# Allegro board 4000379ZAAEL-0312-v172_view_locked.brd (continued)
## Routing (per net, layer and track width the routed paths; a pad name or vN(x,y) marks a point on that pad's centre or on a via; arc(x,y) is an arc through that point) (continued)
MDIDP2: length 28
  TOP w0.091: v3(134.49,109.98) 134.64,110.13 134.64,111.03 134.55,111.12 133.93,111.12 D73.1 133.99,111.57 134.36,111.57 134.45,111.66 134.45,113.2 133.99,113.66 T2.11
  BOTTOM w0.091: U66.65 120.2,96 121.67,97.47 122.83,97.47 134.61,109.26 134.61,109.86 v3(134.49,109.98)
MDIO: length 122.9
  TOP w0.102: E1U1.29 71.32,94.69 70.36,93.73 68.33,93.73 67.94,93.34 67.25,93.34 v1(67.06,93.54)
  TOP w0.127: v1(109.6,68.14) 109.86,68.14 110.87,67.12 110.87,61.02 110.11,60.26 110.11,59.87 SR608.2 ; v1(93.6,73.53) 93.34,73.53 90.04,70.23 v1(90.04,68.71) ; SR57.2 SR70.2 108.14,77.28 108.15,77.26 SC266.1 R234.2 110.16,77.26 v1(110.43,77.53)
  L3 w0.127: v1(109.6,68.14) 109.6,68.33 109.35,68.58 90.17,68.58 v1(90.04,68.71) 89.79,68.45 70.93,68.45 67.56,71.82 67.56,79.76 64.96,82.36 64.96,92.84 65.47,93.34 66.87,93.34 v1(67.06,93.54) ; v1(93.6,73.53) 93.6,73.72 97.66,77.79 110.24,77.79 110.43,77.6 v1(110.43,77.53)
  BOTTOM w0.127: U66.134 115.95,84.53 114.16,82.74 114.16,80.69 111.19,77.72 110.62,77.72 v1(110.43,77.53)
MDIO_0: length 9.8
  TOP w0.102: U1.W6 108.22,52.18 v1(108.15,52.18)
  TOP w0.127: SR608.1 109.73,58.36 108.78,57.4 v1(108.71,57.4)
  L3 w0.127: v1(108.15,52.18) 108.14,52.18 107.84,51.88 107.19,51.88 106.93,52.13 106.93,53.34 107.16,53.57 107.44,53.57 107.75,53.87 107.75,54.91 107.98,55.14 107.98,56.67 v1(108.71,57.4)
MPD: length 9.6
  TOP w0.254: U602.9 v4(54.87,32.45) ; U601.16 58.82,37.26 v4(58.44,37.26)
  BOTTOM w0.254: v4(58.44,37.26) 58.44,37.35 arc(57.9,37.71) 57.26,37.84 56.79,37.84 arc(56.35,37.75) 55.98,37.5 55.6,37.12 arc(55.06,36.31) 54.87,35.35 v4(54.87,32.45)
MSCL0_MSCK: length 5.7
  BOTTOM w0.127: SR603.2 SR611.2 SC502.1 112.8,82.11 112.8,82.82 113.62,83.65 114.07,83.65 114.95,84.53 U66.138
MSCL1_MOSI: length 7.7
  BOTTOM w0.127: SR612.2 SR604.2 ; SR612.2 SC501.1 110.46,82.63 112.23,82.63 113.56,83.97 113.94,83.97 114.45,84.47 U66.140 ; SR612.2 108.97,82.11
MSDA0_MISO: length 10.1
  BOTTOM w0.127: U66.142 113.95,84.42 113.81,84.29 113.43,84.29 112.1,82.95 110.26,82.95 109.86,82.55 107.52,82.55 SC500.1 SR613.2 SR605.2
MSDA1_MCSN: length 12.3
  BOTTOM w0.127: SR606.2 SC499.1 SR614.2 104.68,82.57 107.15,82.57 107.38,82.8 109.73,82.8 110.13,83.21 111.89,83.21 U66.144
OPT_RX_LOS: length 77
  TOP w0.102: U601.31 61.56,32.61 61.65,32.52 61.65,30.72 R605.2 61.42,29.83 v1(61.43,29.82) ; R233.2 98.95,57.21 100.2,57.21 100.9,56.52 102.04,56.52 102.62,55.93 102.62,55.19 U1.AG20
  TOP w0.127: v1(90.36,60.2) 90.36,60.71 92.14,62.48 96.46,62.48 97.66,61.28 97.66,58.24 97.92,57.99 R233.2
  L3 w0.127: v1(61.43,29.82) 60.58,30.67 60.58,32.26 62.23,33.91 62.23,52.26 66.93,56.96 81.03,56.96 84.26,60.2 v1(90.36,60.2)
OPT_TX_SD: length 93.4
  TOP w0.102: U601.23 58.29,33.99 57.34,33.04 v1(57.34,32.26) ; U1.AE12 106.07,54.74 106.4,55.07 106.4,55.3 106.28,55.41 106.28,55.74 107.44,56.9 107.44,57.79 107.82,58.17 108.32,58.17 R277.2
  TOP w0.127: v1(79.95,60.77) 80.58,60.77 87.38,67.56 105.22,67.56 108.46,64.33 108.46,60.71 109.22,59.94 109.22,58.86 108.98,58.63 R277.2
  L3 w0.127: v1(57.34,32.26) 57.34,32.55 59.12,34.33 59.12,37.68 58.8,38 58.8,53.33 64.86,59.39 78.57,59.39 v1(79.95,60.77)
OPT_TXFAULT: length 83.7
  TOP w0.102: R232.2 107.19,57.99 107.19,56.96 106.08,55.85 106.08,55.19 U1.AG12
  TOP w0.127: U601.9 61.96,37.51 62.17,37.72 64.39,37.72 v1(64.45,37.66) 64.52,37.72 64.72,37.72 R606.2 ; v1(82.87,56.96) 82.87,57.02 82.74,57.15 82.74,57.72 81.03,59.44 81.03,60.83 87.5,67.31 103.38,67.31 107.25,63.44 107.25,60.26 107.38,60.13 107.38,58.8 107.55,58.63 R232.2
  L3 w0.127: v1(82.87,56.96) 82.87,56.95 82.87,56.77 81.79,55.69 68.39,55.69 64.01,51.31 64.01,38.1 v1(64.45,37.66)
P4_LED2: length 4.3
  TOP w0.127: v1(109.66,89.98) 108.63,89.98 SC268.2
  BOTTOM w0.127: U66.20 112.08,90.36 111.7,89.98 111.19,89.98 TP12.1 110.55,90.42 110.11,89.98 v1(109.66,89.98)
PON_RX_SLEEP: length 78.6
  TOP w0.102: R258.2 102.36,57.47 103.49,56.34 103.49,55.18 U1.AG18
  TOP w0.127: U601.27 59.96,32.27 v4(59.88,32.19) ; R258.2 102.09,57.99 101.85,58.23 101.85,61.4 99.25,64.01 89.85,64.01 88.2,62.36 v1(88.2,61.66)
  L3 w0.127: v1(88.2,61.66) 81.47,61.66 78.95,59.14 64.99,59.14 59.05,53.21 59.05,38.16 59.37,37.85 59.37,32.7 v4(59.88,32.19)
  BOTTOM w0.127: v4(59.88,32.19) 59.84,32.23 C602.1
PON_TX_DIS: length 69.6
  TOP w0.102: R231.2 99.65,57.47 100.27,57.47 101.03,56.71 102.17,56.71 102.83,56.05 102.83,55.43 102.94,55.31 102.94,55.06 102.62,54.74 U1.AE20
  TOP w0.127: R604.2 65.05,38.24 R613.1 v1(62.93,38.24) 62.18,38.24 61.56,37.62 U601.10 ; v1(89.79,59.37) 89.79,60.55 91.97,62.74 97.35,62.74 98.68,61.4 98.68,58.24 98.93,57.99 R231.2
  L3 w0.127: v1(62.93,38.24) 63.12,38.43 63.12,51.78 67.66,56.32 81.22,56.32 84.26,59.37 v1(89.79,59.37)
PSE_54V0_P1+: length 242.2
  TOP w0.254: v4(31.72,136.75) 31.88,136.91 31.88,137.29 31.97,137.38 U909.28
  TOP w0.635: C252.1 94.61,129.12 T17.45 ; T17.33 106.83,130.91 v2(106.81,130.94)
  TOP w0.762: T1.21 73.91,130.3 73.41,130.81 C244.1 73.79,131.91 74.55,132.67 v2(74.55,136.14) v2(74.55,138.3) ; C252.1 94.11,132.8 93.34,133.56 v2(93.34,135.64) v2(93.34,138.68) ; v2(106.81,130.94) C257.1 ; D814.1 50.24,144.32 C8577.1 v2(52.51,144.32) ; v2(58.1,138.75) 58.55,138.3 58.55,131.13 v2(58.04,130.62) 58.1,130.56 58.1,128.65 57.1,127.65 C8574.1 55.64,127.65 D809.1 51.18,123.2 v2(51.18,123.19) 51.18,118.52 R496.1 51.21,115.61 R1014.1 ; C248.1 v2(125.09,130.94) T2.21
  BOTTOM w0.762: v2(106.81,130.94) 105.28,129.41 D121.2 D102.1 ; v2(106.81,130.94) 105.66,132.08 59.5,132.08 v2(58.04,130.62) 57.17,130.62 56.64,131.15 C8575.1 55.47,131.15 54,129.67 D811.1 ; v2(106.81,130.94) 107.7,131.83 124.21,131.83 v2(125.09,130.94) 123.52,130.94 D117.2 D84.1 ; 53.71,141.73 D813.1 56.52,138.93 C8576.1 56.53,138.75 v2(58.1,138.75) 58.74,138.75 61.34,136.14 v2(74.55,136.14) 92.84,136.14 v2(93.34,135.64) ; 53.71,141.73 D820.C 49.74,142.22 48.26,143.7 33.46,143.7 32.32,142.56 32.32,139 31.78,138.46 31.78,137.62 C8573.1 31.8,137.48 31.75,137.43 31.75,136.78 v4(31.72,136.75) ; 53.71,141.73 52.51,142.93 v2(52.51,144.32) ; v2(93.34,138.68) 95.2,140.54 D125.2 D106.1 ; v2(74.55,138.3) 75.11,138.3 D113.2 D80.1 ; v2(51.18,123.19) 51.18,125.13 50.1,126.21 D812.C
PSE_54V0_P1-: length 56.2
  TOP w0.635: C258.1 90.55,131.03 91.53,130.05 T17.48
  TOP w0.762: C258.1 90.49,131.97 89.65,131.97 88.9,132.72 v2(88.9,135.13) v2(88.9,137.16)
  BOTTOM w0.762: v2(88.9,135.13) 60.64,135.13 58.4,137.37 C8576.2 54.03,137.37 D813.2 53.84,137.54 F3.2 ; v2(88.9,137.16) 88.9,139.9 D108.1 D126.2
PSE_54V0_P2-: length 36.3
  TOP w0.762: T1.24 C245.1 69.47,131.91 68.71,132.67 v2(68.71,137.16) ; v2(55.94,140.78) 53.7,143.02 51.62,143.02 C8577.2
  BOTTOM w0.762: D82.1 D114.2 68.71,140.03 v2(68.71,137.16) 61.98,137.16 59.05,140.08 56.64,140.08 v2(55.94,140.78)
PSE_54V0_P3-: length 85.2
  TOP w0.762: v2(121.79,138.05) v2(121.79,133.1) 121.79,132.67 120.9,131.78 C249.1 120.52,130.81 121.28,130.05 121.28,129.02 ; v2(57.34,131.83) 56.52,131 56.52,130.3
  TOP w1.016: C8574.2 56.52,130.3
  BOTTOM w0.762: v2(121.79,138.05) 121.79,139.39 D118.2 D86.1 ; v2(121.79,133.1) 58.61,133.1 v2(57.34,131.83)
PSE_54V0_P4-: length 69.9
  TOP w0.635: C253.1 103.77,132.68 T17.36
  TOP w0.762: v2(102.74,138.94) v2(102.74,134.11) 102.74,133.56 103.5,132.8 C253.1
  BOTTOM w0.762: v2(102.74,138.94) 102.74,139.01 D122.2 D104.1 ; F2.1 53.52,133.99 D811.2 53.86,133.72 55.07,132.51 C8575.2 57.99,134.11 v2(102.74,134.11)
PSE_SCL: length 16
  TOP w0.127: U909.3 33.27,133.54 33.53,133.79 33.53,134.37 32.96,134.94 28.96,134.94 26.67,132.65 25.15,132.65 24.32,133.48 24.32,135.19 24.27,135.24 R352.1 U22.6
PSE_SDA: length 17.4
  TOP w0.127: U22.7 R353.1 24.69,135.24 24.6,135.15 24.6,133.58 25.27,132.91 26.54,132.91 28.83,135.19 33.08,135.19 33.78,134.49 33.78,133.68 33.92,133.54 ; 33.92,133.54 34.44,133.54 34.57,133.41 U909.5 ; 33.92,133.54 U909.4
PTP_SYNC: length 8.9
  BOTTOM w0.127: SR390.1 112.78,78.11 115.59,80.92 115.59,83.21 116.95,84.56 U66.130
PWR_0V9_PLL5: length 6.2
  TOP w0.254: 106.1,52.68 U1.AA12 ; 106.1,52.68 106.09,52.69 U1.AA14 ; 106.1,52.68 v1(106.48,53.06)
  BOTTOM w0.254: v1(106.48,53.06) 106.67,53.26 C188.1
  BOTTOM w0.305: FB7.2 106.05,57.06 106.6,56.51 C181.1 106.67,55.62 C194.1 C188.1
PWR_1V8_XFI0: length 3.5
  TOP w0.254: v1(104,53.96) 104.46,53.5 U1.AC16
  BOTTOM w0.305: v1(104,53.96) 104.4,54.36 C180.2 104.4,54.93 104.76,55.29 C235.1 104.76,55.91 FB10.2
PWR_1V8_XFI1: length 7.1
  TOP w0.254: U1.AA8 v1(107.33,52.31)
  BOTTOM w0.203: v1(107.33,52.31) 107.68,52.65 109.57,52.65 C187.2
  BOTTOM w0.305: FB6.2 112.74,52.78 C236.1 109.97,52.78 C187.2
PWR_1V8_XFI2: length 8.9
  TOP w0.254: U1.U8 107.72,51.05 107.42,50.75 v1(107.37,50.75)
  BOTTOM w0.127: 112.73,52.01 C239.1
  BOTTOM w0.203: C193.2 110.71,51.55 110.52,51.36 108.69,51.36 108.38,51.05 107.76,51.05 107.45,50.75 v1(107.37,50.75)
  BOTTOM w0.305: C193.2 110.95,51.63 111.32,52.01 114.39,52.01 114.73,52.35 FB5.2
PWR_DG: length 4.6
  TOP w0.254: v1(100.81,49.94) 100.81,49.85 U1.P25
  BOTTOM w0.203: R66.2 97.31,49.01 R28.2 98.76,49.53 100.08,49.53 100.48,49.94 v1(100.81,49.94)
RESET#: length 14.6
  TOP w0.127: SR143.2 117.78,80.01 116.13,81.66 116.13,84.07 116.48,84.43 SC168.1 116.68,84.43 SR128.1 116.68,86.18 v1(116.61,86.25)
  BOTTOM w0.203: U66.131 116.7,86.16 v1(116.61,86.25)
RESET_BUTTON_N: length 183.5
  TOP w0.102: U1.T3 109.7,50.5 110.16,50.5 110.26,50.6 111.91,50.6 112,50.69 116.55,50.69 118.31,52.45 123.83,52.45
  TOP w0.127: R810.1 50.1,159.26 50.09,159.25 C810.1 C981.2 R809.1 50.09,153.62 63.37,140.34 v1(63.37,95.5) ; v1(121.16,67.06) 121.16,58.23 124.4,54.99 124.4,53.02 123.83,52.45
  L3 w0.127: v1(121.16,67.06) 121.13,67.08 69.57,67.08 65.6,71.06 65.6,79.25 63.37,81.47 v1(63.37,95.5)
RESET_PHY_N: length 109.2
  TOP w0.102: E1R22.1 67.56,94.23 v1(67.22,94.58)
  TOP w0.127: v1(109.57,61.18) 109.03,61.72 109.03,65.6 107.44,67.18 v1(107.44,67.75) ; U1.AB27 99.3,52.92 98.84,52.92 98.6,52.68 98.1,52.68 96.8,53.98 95.2,53.98 92.63,56.54 92.63,61.14 v1(92.84,61.34)
  L3 w0.127: v1(107.44,67.75) 107.28,67.59 70.33,67.59 66.48,71.44 66.48,79.63 64.14,81.98 64.14,93.92 65.02,94.81 66.99,94.81 v1(67.22,94.58) ; v1(92.84,61.34) 93.28,61.79 108.97,61.79 v1(109.57,61.18)
RESET_RTL8261BE_N: length 14.3
  TOP w0.102: E1U1.28 71.34,95.09 71.18,94.93 69.9,94.93 ; 69.58,94.74 68.01,94.74 67.12,95.63 67.12,100.46 67.88,101.22 68.64,101.22 ; 68.64,101.22 E1R3.2 ; 68.64,101.22 EC340.2
  TOP w0.127: E1R22.2 E1R20.1 69.9,94.93
RESET_SUICIDE: length 4
  TOP w0.102: U1.AH6 108.55,55.59 108.55,56.29 109.97,57.71 v1(110.4,57.71)
  BOTTOM w0.127: R963.1 110.74,58.04 v1(110.4,57.71)
RESETB: length 7
  TOP w0.127: SR143.1 126.06,80.01 SR90.2 SR88.2 128.31,80.06 SD2.A 129.2,80.77 SC254.1 130.24,80.76 U108.RST
RSET0: length 2.4
  TOP w0.203: E1R5.2 80.57,100.99 80.57,99.34 80.31,99.09 E1U1.68
RSSI: length 3.8
  BOTTOM w0.381: R660.1 56.29,25.5 56.86,24.93 56.86,23.84 56.47,23.46 R655.2 56.02,23.29 Q603.3
RSSI_IN: length 9.6
  TOP w0.229: C603.1 58.89,31.94 59.49,32.54 arc(59.54,32.61) 59.56,32.7 U601.26
  TOP w0.508: v4(57.15,30.8) 58.05,30.8 58.83,31.58 C603.1
  BOTTOM w0.508: R660.2 57.61,26.12 57.61,27.62 56.83,28.41 56.83,30.48 v4(57.15,30.8)
RSV_TEST0: length 1.8
  TOP w0.305: SR536.1 124.14,92.33 v1(123.92,92.55)
  BOTTOM w0.203: U66.80 123.46,92.86 123.77,92.55 v1(123.92,92.55)
RXIN1_N: length 5.9
  TOP w0.107: U602.4 55.31,28.89 55.63,29.21 58.69,29.21 59.88,30.4 C600.2
RXIN1_P: length 5.6
  TOP w0.107: C601.2 59.64,30.56 58.57,29.49 55.6,29.49 55.4,29.69 U602.5
RXIN_N: length 2.2
  TOP w0.107: U601.28 60.36,32.86 60.43,32.79 60.43,31.36 60.29,31.23 C601.1
RXIN_P: length 2.4
  TOP w0.107: C600.1 60.5,31.03 60.71,31.24 60.71,32.77 60.76,32.82 U601.29
RXOUT+: length 1.9
  TOP w0.107: C610.2 64.06,34.33 62.7,34.33 62.64,34.39 U601.3
RXOUT-: length 1.9
  TOP w0.107: C609.2 64.08,34.05 62.75,34.05 62.69,33.99 U601.2
RXOUTN: length 73.6
  TOP w0.107: C609.1 64.96,34.06 66.44,34.06 v1(66.67,33.83) ; v1(87.25,57.34) 87.06,57.53 87.06,62.36 89.6,64.9 101.41,64.9 103.25,63.06 103.25,60.39 104.01,59.63 104.01,56.95 104.24,56.72 104.24,55.67 arc(104.23,55.58) 104.19,55.5 arc(104.19,55.49) 104.19,55.49 arc(104.16,55.45) 104.13,55.41 arc(104.12,55.39) 104.1,55.37 104.1,55.37 arc(104.05,55.3) 104.04,55.22 104.04,54.88 U1.AF17
  L3 w0.099: v1(66.67,33.83) 66.89,34.05 67.96,34.05 68.96,35.05 68.96,50.48 71.14,52.66 82.95,52.66 87.06,56.77 87.06,57.15 v1(87.25,57.34)
RXOUTP: length 73.5
  TOP w0.107: v1(66.67,34.57) 66.44,34.34 64.96,34.34 C610.1 ; v1(86.55,57.34) 86.78,57.57 86.78,62.47 89.48,65.18 101.53,65.18 103.53,63.17 103.53,60.5 104.29,59.74 104.29,57.06 104.52,56.83 104.52,55.67 arc(104.5,55.51) 104.43,55.36 arc(104.39,55.29) 104.35,55.23 U1.AG16
  L3 w0.099: v1(86.55,57.34) 86.76,57.13 86.76,56.89 82.82,52.96 71.01,52.96 68.66,50.61 68.66,35.18 67.83,34.35 66.9,34.35 v1(66.67,34.57)
S0RXN: length 7.9
  BOTTOM w0.091: U66.122 118.95,84.76 119.04,84.67 119.04,84.14 118.65,83.74 118.65,83.36 117.73,82.44 117.73,79.68 117.73,77.9 SR259.1
S0RXP: length 8.6
  BOTTOM w0.091: U66.123 118.7,84.28 118.3,83.88 118.3,83.5 117.38,82.59 117.38,79.68 117.39,77.87 SR260.1
S0TXN: length 8.7
  BOTTOM w0.091: U66.119 119.7,83.78 119.34,83.42 119.34,83.04 119.01,82.71 119.01,80.12 119.79,79.35 119.79,77.87 SC85.1
S0TXP: length 8
  BOTTOM w0.091: U66.120 119.38,84.69 119.38,83.95 119,83.57 119,83.19 118.67,82.85 118.67,79.98 119.44,79.2 119.44,77.9 SC84.1
SCL_M: length 2.7
  BOTTOM w0.127: U604.6 47.39,25.46 R630.1 47.86,25.49 48.23,25.49 R639.1
SDA_M: length 2.6
  BOTTOM w0.127: U604.5 47.57,26.11 R629.1 47.87,25.92 48.27,25.92 R633.1
SEL_XTAL: length 3.1
  TOP w0.254: v1(121.16,86.79) 121.11,86.84 121.04,86.84 120.83,87.06 SR73.2 120.51,86.27 SR72.1
  BOTTOM w0.203: v1(121.16,86.79) 121.2,86.83 121.48,86.83 121.76,87.11 U66.103
SPF_CS#: length 27.9
  BOTTOM w0.089: 111.85,87.46 112,87.61 U66.9
  BOTTOM w0.127: 111.85,87.46 111.13,86.74 109.98,86.74 109.6,86.36 105.38,86.36 103.82,87.92 103.82,95.76 102.3,97.28 97.79,97.28 97.54,97.03 TP24.1 97.54,95.47 97.56,95.44 ; 97.56,95.44 SC256.1 ; 97.56,95.44 SR142.2
SPF_SCK: length 8
  BOTTOM w0.127: SR140.2 SC250.1 106.72,84.29 107.04,83.97 108.61,83.97 TP21.1 109.41,85.03 110.36,85.98 111.63,85.98 112.02,86.36 U66.4
SPF_SI: length 7.6
  BOTTOM w0.127: SR141.2 SC252.1 106.7,85.68 106.87,85.85 108.33,85.85 TP22.1 109.54,85.53 110.24,86.23 111.44,86.23 112.07,86.86 U66.6
SPF_SO: length 21.6
  BOTTOM w0.127: SR139.2 SC251.1 102.04,96.77 TP23.1 103.57,95.25 103.57,87.77 105.23,86.11 109.73,86.11 110.11,86.49 111.25,86.49 112.13,87.36 U66.8
SPI1_CS#: length 3.8
  BOTTOM w0.127: 97.52,92.65 98.43,92.65 98.89,93.11 U7.1 ; 97.52,92.65 SR80.2 ; 97.52,92.65 97.52,93.6 SR142.1
SPI1_HOLD#: length 2.6
  BOTTOM w0.508: SR81.2 SC523.1 100.16,85.64 U7.7
SPI1_SCK: length 5.2
  BOTTOM w0.127: U7.6 101.43,85.73 102.66,84.5 SR82.2 104.91,84.5 SR140.1
SPI1_SI: length 3.3
  BOTTOM w0.127: U7.5 102.7,86.21 103.49,85.42 SR85.2 103.96,85.41 SR141.1
SPI1_SO: length 6.1
  BOTTOM w0.127: SR98.2 97.54,91.65 98.89,91.65 100.16,92.92 U7.2 100.16,95.42 100.15,95.43 SR139.1
SPI1_WP#: length 8.2
  BOTTOM w0.127: SR87.1 SR84.2 100.33,90.68 101.73,92.07 101.73,93.54 101.43,93.83 U7.3
SWITCH_INT_N: length 58
  TOP w0.127: v4(109.35,73.09) 109.35,72.33 108.33,71.31 108.33,66.67 109.28,65.72 109.28,62.17 109.54,61.91 v1(109.54,61.85) ; v1(92.2,61.59) 92.32,61.48 92.32,56.4 95.06,53.66 96.71,53.66 97.97,52.4 98.78,52.4 U1.AA28
  L3 w0.127: v1(92.2,61.59) 92.65,62.04 109.41,62.04 109.54,61.91 v1(109.54,61.85)
  BOTTOM w0.127: U66.132 116.45,84.44 115.34,83.33 115.34,81.05 112.2,77.91 112.2,75.95 v4(109.35,73.09)
SWITCH_RESET_N: length 62.3
  TOP w0.102: 96.84,52.07 97.54,52.07 97.74,51.87 98.68,51.87 99.35,52.54 U1.AA26
  TOP w0.127: 96.84,52.07 96.22,52.07 92.01,56.27 92.01,60.83 v1(91.79,61.06) ; SR63.2 115.82,85.37 SR128.2 115.82,85.37 115.82,80.47 v1(115.09,79.73) ; v1(110.64,73.25) 108.58,71.2 108.58,66.8 109.54,65.85 109.54,62.67 v1(110.17,62.04)
  L3 w0.127: v1(110.17,62.04) 109.92,62.29 92.14,62.29 91.63,61.79 91.63,61.21 v1(91.79,61.06)
  BOTTOM w0.127: v1(115.09,79.73) 113.28,77.93 113.28,75.9 v1(110.64,73.25)
TX_BURST: length 79.8
  TOP w0.102: U1.AF13 105.75,54.87 105.75,55.29 105.88,55.42 105.88,55.97 106.93,57.02 106.93,58.37 R621.1
  TOP w0.127: R699.2 65.1,39.61 64.83,39.88 v1(64.71,39.88) 62.44,39.88 R623.1 ; R621.1 106.95,58.63 107.12,58.8 107.12,60.01 107,60.13 107,63.25 103.19,67.06 87.63,67.06 81.28,60.71 81.28,59.56 v1(83.38,57.47)
  L3 w0.127: v1(83.38,57.47) 83.38,56.83 81.98,55.44 69.53,55.44 64.9,50.8 64.9,40.07 v1(64.71,39.88)
TXIN_N: length 69.7
  TOP w0.107: C271.2 106.01,62.07 106.01,62.65 102.46,66.19 88.34,66.19 82.73,60.58 v1(82.28,60.58) ; U601.14 60.03,36.98 60.03,39.26 v1(59.79,39.49)
  L3 w0.099: v1(59.79,39.49) 60.02,39.72 60.02,51.93 66.23,58.15 80.27,58.15 82.28,60.16 v1(82.28,60.58)
TXIN_P: length 68.7
  TOP w0.107: U601.13 60.31,36.97 60.31,39.27 v1(60.53,39.49) ; v1(82.87,59.99) 82.87,60.33 88.46,65.91 102.35,65.91 105.73,62.53 105.73,62.03 C270.2
  L3 w0.099: v1(82.87,59.99) 82.53,59.99 80.39,57.85 66.36,57.85 60.33,51.82 60.33,39.7 v1(60.53,39.49)
U0RXD: length 3.9
  BOTTOM w0.254: SR159.1 126.19,89.22 125.35,89.22 124.63,89.94 123.4,89.94 123.33,89.86 U66.92
U0TXD: length 3.8
  BOTTOM w0.254: SR158.1 126.32,89.66 125.48,89.66 124.78,90.36 U66.90
UART0_RX: length 30.2
  TOP w0.102: U1.R2 112.15,49.95 112.2,50 119.72,50
  TOP w0.127: 119.72,50 120.09,50.37 121.51,50.37 121.72,50.16 123.44,50.16 125.29,52.01 135.64,52.01 136.65,50.99 137.24,50.99 R955.2 137.62,49.69 R958.2
UART0_RX_1: length 5
  TOP w0.127: R955.1 139.58,50.61 D903.1 143.31,50.36 J7.3
UART0_TX: length 30.9
  TOP w0.102: U1.R4 109.57,49.95 109.87,50.25 110.15,50.25 110.24,50.16 112.07,50.16 112.14,50.23 119.57,50.23 119.94,50.6 R188.1
  TOP w0.127: R188.1 R187.2 121.57,50.72 121.87,50.42 123.32,50.42 125.16,52.26 135.76,52.26 136.78,51.24 137.24,51.24 R27.2
UART0_TX_1: length 5.4
  TOP w0.127: R27.1 139.64,51.63 D904.1 142.36,51.81 J7.2
UPGND: length 38.1
  TOP w0.254: v1(29.4,164.86) 29.59,164.86 29.84,164.61 USB1.B1 ; USB1.A12 29.59,162.69 29.34,162.43 v1(28.98,162.43) ; v2(37.97,154.24) 37.83,154.1 U27.5 ; v2(36.51,155.64) 36.26,155.64 35.92,155.3 U27.6 ; USB1.B12 v1(35.34,165.27) ; USB1.A1 v1(35.62,162.82)
  TOP w0.381: USB1.25 36.79,164.93 ; USB1.25 36.79,162.11 ; USB1.25 37.64,163.52 ; USB1.26 28.15,164.93 ; USB1.26 28.15,162.11 ; USB1.26 27.3,163.52 ; 35.49,164.12 USB1.27 36.46,164.92 ; 27.25,168.57 USB1.30 ; USB1.30 29.05,168.57 ; USB1.30 28.15,167.02 ; 35.89,168.57 USB1.29 ; USB1.29 36.79,167.02 ; USB1.29 37.69,168.57
  TOP w0.508: v2(37.53,149.92) R995.2 ; R985.2 v2(33.4,149.92)
  BOTTOM w0.381: 36.79,162.11 USB1.25 ; USB1.25 36.79,164.93 ; USB1.25 37.64,163.52 ; 27.3,163.52 USB1.26 ; USB1.26 28.15,164.93 ; USB1.26 28.15,162.11 ; 36.79,167.02 USB1.29 ; USB1.29 35.89,168.57 ; USB1.29 37.69,168.57 ; 27.25,168.57 USB1.30 ; USB1.30 29.05,168.57 ; USB1.30 28.15,167.02 ; 35.49,164.12 USB1.27 36.46,164.92
  vias: v2(26.8,158.56) v2(27.11,154.88) v2(27.18,155.96) v2(27.94,159.77) v2(28,157.35) v2(30.67,157.86) v2(30.73,156.78) v2(30.92,159.77) v2(31.5,154.88) v2(31.69,161.93) v2(31.94,165.29) v2(33.21,161.29) v2(33.66,158.81) v2(33.78,156.53) v2(35.31,156.59) v2(35.69,160.59) v2(35.88,158.75) v2(35.94,157.73) v2(37.5,150.91) v2(38.42,160.08)
USXGMII0_RD+: length 58.1
  TOP w0.091: v3(110.82,71.78) 111,71.6 111.73,71.6 112.41,70.93 112.41,59.79 R611.1 ; v3(80.39,83.64) 80.23,83.8 80.23,88.73 EC334.1
  L3 w0.084: v3(110.82,71.78) 110.71,71.67 86.06,71.67 82.68,75.05 82.68,79.94 80.24,82.38 80.24,83.49 v3(80.39,83.64)
USXGMII0_RD-: length 58.1
  TOP w0.091: R612.1 112.06,59.79 112.06,70.78 111.59,71.26 110.91,71.26 v3(110.82,71.17) ; EC335.1 79.89,88.73 79.89,83.75 v3(79.78,83.64)
  L3 w0.084: v3(110.82,71.17) 110.68,71.31 85.92,71.31 82.32,74.9 82.32,79.79 79.88,82.23 79.88,83.54 v3(79.78,83.64)
USXGMII0_TD+: length 61
  TOP w0.091: ER359.1 77.6,87.84 77.6,83.79 v3(77.47,83.67) ; C86.1 114.2,59.77 114.2,68.6 v3(114.1,68.71)
  L3 w0.084: v3(77.47,83.67) 77.56,83.58 77.56,82.02 80.35,79.22 80.35,74.65 85.15,69.85 113.87,69.85 114.2,69.52 114.2,68.81 v3(114.1,68.71)
USXGMII0_TD-: length 61.1
  TOP w0.091: v3(78.08,83.67) 77.94,83.81 77.94,87.74 ER360.1 ; v3(114.71,68.71) 114.55,68.55 114.55,59.81 C87.1
  L3 w0.084: v3(78.08,83.67) 77.91,83.5 77.91,82.16 80.71,79.37 80.71,74.8 85.3,70.21 114.02,70.21 114.55,69.67 114.55,68.86 v3(114.71,68.71)
USXGMII1_RD+: length 18.9
  TOP w0.091: R615.1 116.33,59.8 116.33,69.37 v3(116.23,69.47)
  BOTTOM w0.091: v3(116.23,69.47) 116.34,69.58 116.34,70.19 119.42,73.26 119.42,76.43 SC84.2
USXGMII1_RD-: length 18.9
  TOP w0.091: v3(116.84,69.47) 116.68,69.31 116.68,59.77 R616.1
  BOTTOM w0.091: SC85.2 119.76,76.41 119.76,73.12 116.69,70.05 116.69,69.62 v3(116.84,69.47)
USXGMII1_TD+: length 18
  TOP w0.091: v3(117.25,73.18) 117.37,73.05 117.37,71.73 118.27,70.83 118.27,59.77 C89.1
  BOTTOM w0.091: SR260.2 117.4,76.42 117.4,73.33 v3(117.25,73.18)
USXGMII1_TD-: length 18
  TOP w0.091: v3(117.86,73.18) 117.72,73.04 117.72,71.87 118.62,70.97 118.62,59.8 C93.1
  BOTTOM w0.091: v3(117.86,73.18) 117.74,73.29 117.74,76.42 SR259.2
USXGMII_RD+_RTL8261BE: length 3.6
  TOP w0.091: E1U1.44 76.63,91.96 76.63,90.89 77.65,89.87 77.65,89.25 ER359.2
USXGMII_RD-_RTL8261BE: length 3.6
  TOP w0.091: E1U1.45 76.97,91.96 76.97,91.03 77.99,90.01 77.99,89.25 ER360.2
USXGMII_TD+_RTL8261BE: length 3.7
  TOP w0.091: E1U1.49 78.57,91.96 78.57,90.95 79.07,90.45 79.66,90.45 80.23,89.88 80.23,89.49 EC334.2
USXGMII_TD-_RTL8261BE: length 3.7
  TOP w0.091: EC335.2 79.89,89.49 79.89,89.74 79.52,90.11 78.93,90.11 78.23,90.81 78.23,91.96 E1U1.48
VAA_1V8: length 17.7
  TOP w0.203: 101.62,49.03 101.62,49.83 v1(101.63,49.83)
  TOP w0.254: v1(107.26,48.26) 106.9,48.62 U1.M10 ; U1.T24 101.21,50.25 101.62,49.83 ; 101.62,49.03 U1.M22 101.62,48.22 v1(101.62,48.21)
  TOP w0.305: v1(103.23,46.6) 103.25,46.6 U1.H18
  BOTTOM w0.203: C228.2 100.14,49.02 100.6,49.48 101.27,49.48 v1(101.63,49.83) ; 106.24,47.82 106.82,47.82
  BOTTOM w0.254: C216.2 103.23,45.31 ; C213.2 103.23,44.63
  BOTTOM w0.305: 106.82,47.82 v1(107.26,48.26) 107.43,48.43 C224.2 ; v1(101.62,48.21) 101.63,48.21 C220.2 102.04,47.69 103.14,46.6 v1(103.23,46.6) 105.02,46.6 106.24,47.82
  BOTTOM w0.508: v1(103.23,46.6) 103.23,44.32 102.72,43.81 FB13.2
VAA_1V8_OTP: length 5.3
  TOP w0.254: v1(107.37,53.16) U1.AC8
  BOTTOM w0.152: 108.46,53.57 107.78,53.57 v1(107.37,53.16)
  BOTTOM w0.203: 108.46,53.57 108.56,53.47 109.17,53.47 109.68,53.98 110.04,53.98 C1014.1
  BOTTOM w0.305: FB15.2 111.18,54.58 110.83,54.24 C1014.1
VAA_1V8_PLL: length 5.8
  TOP w0.254: U1.AC14 v1(105.61,53.84) 105.69,53.91 106.5,53.91 U1.AC10 106.9,53.59 v1(107.34,54.03)
  BOTTOM w0.305: C1013.1 105.6,53.85 v1(105.61,53.84) ; C1.1 107.27,55.28 107.27,55 107.26,54.99 C210.1 107.26,54.11 v1(107.34,54.03)
  BOTTOM w0.508: C1.1 107.52,55.58 107.52,56.47 FB14.2
VAA_1V8_PVT: length 18.6
  TOP w0.254: U1.T6 108.5,50.25 108.18,50.57 v1(108.13,50.57) ; v1(100.71,50.61) 100.71,50.56 U1.T25
  L3 w0.178: 106.93,50.32 107.72,50.32
  L3 w0.203: v1(100.71,50.61) 100.88,50.61 101.22,50.27 102.06,50.27 103.73,48.59 105.54,48.59 105.71,48.77 105.71,49.99 105.89,50.16 106.78,50.16 106.93,50.32 ; 107.72,50.32 107.98,50.57 v1(108.13,50.57)
  BOTTOM w0.127: 111.88,50.45 C227.1
  BOTTOM w0.305: FB12.2 115.59,50.45 C231.1 C223.1 C219.1 108.25,50.45 v1(108.13,50.57)
VLD: length 9
  TOP w0.102: 49.91,38.26 C607.1
  TOP w0.508: L600.1 R614.1 52.44,39.1 51.59,38.26 49.26,38.26 R610.2
VOUT: length 6.2
  TOP w0.254: 32.19,151.51 32.78,152.1 U27.15
  TOP w0.508: 32.19,151.51 31.75,151.07 27.18,151.07
VREFCA: length 114.8
  TOP w0.178: U12.M8 112.14,23.99 111.74,24.38 110.37,24.38 v1(109.25,23.27) ; v1(89.51,23.47) 90.43,24.39 91.37,24.39 91.77,23.99 U13.M8
  TOP w0.254: U1.P22 102.03,49.43 v1(102.39,49.07) ; U12.H1 118.29,20.79 v1(118.38,20.66) ; v1(106.53,49.73) 106.82,49.44 U1.P10 ; v4(98.48,20.73) 98.45,20.79 97.37,20.79 U13.H1
  TOP w0.305: v1(104.9,47.37) 104.91,47.37 U1.H14
  L3 w0.508: v2(123.63,47.75) 124.21,47.18 124.21,45.02 127.51,41.72 127.51,27.88 129.86,25.53 129.86,18.61 v2(130,18.47)
  BOTTOM w0.102: C957.1 107.9,21.82 ; C111.1 99.26,20.79 ; C98.1 109.63,21.97 ; 89.67,22.47 89.49,22.3 C956.1
  BOTTOM w0.203: C155.1 102.61,48.2 103.06,47.75 103.57,47.75 103.67,47.85 104.3,47.85 104.34,47.81 C117.1 104.83,47.37 v1(104.9,47.37) 105.17,47.37 C154.1 106.02,48.22 106.02,48.56 106.53,49.07 v1(106.53,49.73) 106.55,49.73 106.88,49.4 109.25,49.4
  BOTTOM w0.254: C101.1 118.82,20.75 118.46,20.74 v1(118.38,20.66) ; 120.36,49 119.62,49.73 109.58,49.73 109.25,49.4 ; 109.18,21.97 109.18,23.19 v1(109.25,23.27) ; v1(102.39,49.07) 102.61,48.85 C155.1
  BOTTOM w0.305: 89.99,22.21 89.58,22.21 C956.1 89.49,23.45 v1(89.51,23.47) ; C153.1 106.49,49.72 106.5,49.73 v1(106.53,49.73)
  BOTTOM w0.381: v1(118.38,20.66) 118.32,20.6 118.33,20.05 118.01,19.74 116.25,19.74 115.92,20.08 115.92,20.51 115.68,20.75 115.16,20.75 113.94,21.97 108.86,21.97 108.69,21.79 107.57,21.79 106.56,20.79 98.55,20.79 v4(98.48,20.73) 98.39,20.82 94.68,20.82 93.34,22.15 90.05,22.15 89.99,22.21
  BOTTOM w0.508: 120.36,49 122.71,49 123.63,48.07 v2(123.63,47.75) ; 118.33,20.05 121.08,17.3 127.84,17.3 128.02,17.48 128.02,17.5 128.04,17.53 v2(128.93,17.53)
  vias: v2(128.91,18.47) v2(130,17.55)
XI: length 3
  TOP w0.127: v1(125.03,86.68) 125.16,86.8 125.62,86.8 SR422.2
  BOTTOM w0.127: v1(125.03,86.68) 124.76,86.95 123.14,86.95 U66.104
XO: length 3
  TOP w0.127: SR423.2 125.49,87.31 125.16,87.31 v1(125.03,87.44)
  BOTTOM w0.127: v1(125.03,87.44) 124.86,87.27 123.14,87.27 U66.102
XTAL_N_50M: length 1.7
  TOP w0.127: E1R1.2 81.21,98.2 80.52,98.2 80.43,98.29 E1U1.66
XTAL_P_50M: length 1.6
  TOP w0.127: E1U1.65 81.47,97.89 E1R2.2
N2858156: length 8.3
  TOP w0.127: SR423.1 126.73,87.57 126.75,87.59 127.4,87.59 SR78.1 129.21,87.65 SC164.1 132.96,87.65 SY3.1
N2858168: length 5.5
  TOP w0.127: SR422.1 127.74,86.68 128.33,86.09 ; 128.33,86.09 128.36,86.06 128.97,86.68 129.91,86.68 SC165.1 130.05,86.66 SY3.3 ; 128.33,86.09 SR78.2
N3905780: length 1.3
  TOP w0.305: SR485.1 117.86,94.74 v1(117.86,94.11)
  BOTTOM w0.254: U66.55 117.7,94.27 v1(117.86,94.11)
N4210476: length 1
  BOTTOM w0.127: SR175.2 105.44,86.97 TP10.1
N4364334: length 1
  BOTTOM w0.127: SR603.1 TP26.1
N4425325: length 2.1
  TOP w0.127: v1(121,91.71) 120.74,91.71 120.46,91.44 TP31.1
  BOTTOM w0.127: U66.85 122.2,91.51 121.21,91.51 v1(121,91.71)
N4425340: length 3.3
  TOP w0.127: TP32.1 119.9,91.89 120.49,91.89 120.75,92.15 121.43,92.15 v1(121.64,91.94)
  BOTTOM w0.127: v1(121.64,91.94) 121.81,92.11 U66.83
N4758164: length 1
  BOTTOM w0.127: SR604.1 TP27.1
N4760323: length 1
  BOTTOM w0.127: TP28.1 SR605.1
N4760327: length 1
  BOTTOM w0.127: SR606.1 TP29.1
N17215587: length 3.8
  TOP w0.508: R977.2 R976.1 ; R976.1 C1002.1 ; R976.1 133.75,50.65 PU902.3
N17224518: length 3.1
  TOP w0.508: PU902.4 128.35,50.65 R983.1 R984.2 C1006.2
N17229070: length 3.8
  TOP w0.508: R979.2 R978.1 ; R978.1 C1007.1 ; R978.1 132.04,54.96 PU908.3
N17229197: length 1.3
  TOP w0.508: C1011.1 128.17,54.94 PU908.4
N17760544: length 6.3
  TOP w0.102: R198.1 90.62,50.86 89.98,50.86 89.68,50.56 C161.1 88.85,49.99 87.26,48.4 Y3.1
N17761068: length 3.9
  TOP w0.102: 88.99,50.69 88.99,50.51 88.45,49.96 87.69,49.96 Y3.3 ; 88.99,50.69 C162.1 ; 88.99,50.69 89.42,50.69 89.85,51.12 90.56,51.12 R197.1
N17882333: length 1.6
  TOP w0.102: U1.AC4 108.84,53.67 v1(108.84,53.92)
  BOTTOM w0.127: v1(108.84,53.92) 109.46,54.54 R256.2
N17882335: length 4.8
  TOP w0.102: v1(111.51,55.44) 110.81,54.74 110.11,54.74 109.99,54.62 109.61,54.62 109.37,54.38 U1.AD4
  BOTTOM w0.127: v1(111.51,55.44) 112.1,55.44 112.75,56.08 R254.2
N17882341: length 3.7
  TOP w0.102: v1(108.13,53.14) 108.15,53.11 108.99,53.11 109.13,52.97 U1.AB3
  BOTTOM w0.127: v1(108.13,53.14) 108.2,53.06 109.37,53.06 109.65,53.34 R257.2
N17882343: length 3.9
  TOP w0.102: U1.AC2 110,53.4 111.95,53.4 112.78,54.23 R255.2
N17882349: length 5.9
  TOP w0.091: R611.2 112.42,58.34 112.42,57.45 111.36,56.39 110.03,56.39 109.55,55.92 109.55,55.4 U1.AG4
N17882351: length 5.1
  TOP w0.091: R612.2 112.08,58.31 112.08,57.59 111.22,56.73 109.88,56.73 109.21,56.06 109.21,55.61 U1.AH4
N17883614: length 4.2
  TOP w0.102: U1.AE18 103.48,54.74 103.8,55.06 103.8,55.32 103.69,55.42 103.69,56.45 103,57.15 103,57.67 R154.1
N18711366: length 4.7
  TOP w0.127: v4(57.78,36.62) 57.8,36.6 57.8,36.4 58.22,35.99 U601.18
  BOTTOM w0.254: v4(57.78,36.62) 57.76,36.62 57.75,36.61 57.4,36.61 56.87,36.07 L602.1 R620.1
N18711370: length 2.6
  TOP w0.508: L603.1 56.96,33.44 56.65,33.13 v4(56.65,33.11)
  BOTTOM w0.381: R620.2 L602.2 56.87,33.34 56.65,33.13 v4(56.65,33.11)
N18711395: length 2.3
  BOTTOM w0.508: R635.1 60.13,25.23 v4(60.67,24.7)
N18711397: length 1.9
  BOTTOM w0.508: v4(62.97,24.61) 62.3,23.94 Q600.D
N18711401: length 2.6
  BOTTOM w0.127: R652.1 63.63,26.57
  BOTTOM w0.508: Q602.S 63.63,27.84 63.63,25.54 D601.A
N18711446: length 12.7
  TOP w0.381: v4(64.67,32.87) 64.63,32.83 63.59,32.83 63.19,32.42 63.19,31.53 62.91,31.25 62.91,27.28 R636.2 61.77,27.06 C621.2
  BOTTOM w0.381: R648.1 63.09,35.89 63.93,35.89 64.55,35.27 64.55,32.99 v4(64.67,32.87)
N18711477: length 8.9
  TOP w0.381: Q601.3 53.28,23.75 52.83,23.3 v4(52.58,23.3) ; v4(52.58,23.3) 52.58,23.17 52.96,22.79 54.2,22.79 54.58,23.17 54.58,24.27 54.89,24.57 Q601.5 ; v4(52.58,23.3) 52.45,23.43 52.45,24.19 52.83,24.57 Q601.2
  BOTTOM w0.381: Q603.4 52.59,23.29 v4(52.58,23.3) 51.83,23.3 R656.1
N18711479: length 3.3
  TOP w0.381: v4(54.21,24.91) 54.28,24.91 54.59,25.22 Q601.6
  BOTTOM w0.381: v4(54.21,24.91) 54.53,24.59 Q603.1 55.93,24.59 R655.1
N18711481: length 0.9
  TOP w0.381: R638.2 56.04,23.92 Q601.4
N18711483: length 3.8
  TOP w0.381: Q601.1 53.48,25.22 54.01,25.75 55.68,25.75 56.1,25.32 56.1,24.78 R637.2
N18711507: length 7.3
  BOTTOM w0.381: R662.1 53.82,25.65 53.41,25.24 Q603.6 52.23,24.59 R656.2 52.05,23.94 Q603.5 Q603.2
N18711644: length 3.1
  TOP w0.381: R614.2 L600.2 57.28,37.89 56.96,37.57 L601.1
N18712169: length 7
  BOTTOM w0.381: R651.1 62.99,35.38 63.72,35.38 64.03,35.07 64.03,32.52 64.15,32.4 64.15,30.37 63.63,29.85 Q602.G
N18712178: length 1.8
  BOTTOM w0.508: R635.2 60.15,27.61 Q602.D
N18712277: length 1.4
  TOP w0.229: U601.7 62.99,35.99 63.32,36.32 R617.2
N18712349: length 2.2
  TOP w0.127: U601.11 61.16,37.74 R623.2
N18712445: length 1.1
  TOP w0.406: U602.7 53.96,31.29 v4(53.8,31.29)
N18842601: length 4
  TOP w0.127: R987.2 33.6,13.19 Q1.B 33.59,14.62 CE20.1 R173.1
N18842628: length 18.1
  TOP w0.127: D803.C 50.35,5.53 49.66,6.22 39.39,6.22 R800.1
N18842711: length 3.9
  TOP w0.127: R175.2 CE21.1 38.73,14.62 Q2.B 38.75,13.19 R986.2
N18842733: length 3.6
  TOP w0.127: R986.1 R801.2 38.06,11.35 Q2.C
N18842763: length 17.8
  TOP w0.127: R801.1 40.26,8.64 41.78,7.11 50.67,7.11 51.44,6.35 51.44,3.81 50.92,3.3 D810.C
N18842823: length 3.6
  TOP w0.127: R987.1 R800.2 32.91,11.35 Q1.C
N18843479: length 4.1
  TOP w0.127: R989.2 76.4,13.19 Q5.B 76.39,14.62 CE28.1 R177.2
N18843504: length 16
  TOP w0.127: R803.1 79.04,10.49 82.55,6.99 88.9,6.99 90.35,5.53 D805.C
N18843506: length 3.6
  TOP w0.127: Q5.C 75.71,11.35 R803.2 R989.1
N18851579: length 5.6
  TOP w0.127: SW800.1 50.1,164.91 R810.2
N19004192: length 5.6
  TOP w0.305: J7.1 143.37,55.39 C925.1 139.82,55.38 C28.1 138.74,55.37 R956.2
N19017731: length 3.9
  TOP w0.127: R990.2 49.99,13.19 Q6.B 49.97,14.62 CE30.1 R178.2
N19017798: length 15.5
  TOP w0.127: R805.1 52.47,9.53 57.91,9.53 61.59,5.84 61.59,3.81 61.08,3.3 D804.C
N19017800: length 3.6
  TOP w0.127: R990.1 R805.2 49.29,11.35 Q6.C
N19057080: length 1.3
  TOP w0.762: C249.2 R243.1
N19057084: length 1.3
  TOP w0.762: C248.2 R242.1
N19057088: length 1.3
  TOP w0.762: C247.2 R240.1
N19057092: length 1.3
  TOP w0.762: C246.2 R239.1
N19057096: length 21.5
  TOP w0.762: R242.2 v2(125.09,136.78) ; R239.2 v2(132.72,136.78) ; R243.2 v2(120.52,136.78) ; v2(128.91,136.78) R240.2
  BOTTOM w0.762: C234.1 132.72,138.75 v2(132.72,136.78) v2(128.91,136.78) v2(125.09,136.78) v2(120.52,136.78)
N19110181: length 1.3
  BOTTOM w0.127: R200.1 110.62,48.54 TP1.1
N19140562: length 3.4
  BOTTOM w0.102: R641.1 45.12,22.57 45.12,24.48 45.45,24.81 U604.7
N19148827: length 3
  TOP w0.305: R1008.2 R1007.1 28.12,68.53 28.34,68.75 PU23.5
N19149157: length 1.6
  TOP w0.254: 133.17,23.52 133.4,23.29 U904.5 ; 133.17,24.08 133.18,24.09 U904.3
N19149206: length 1.3
  TOP w0.254: 136.33,24.45 136.46,24.32 136.46,23.87 136.28,23.69 U904.7
N19149209: length 2.1
  TOP w0.305: PU23.6 28.34,64.57 28.03,64.26 27.43,64.26 27.05,63.88 C8566.1
N19149443: length 1.3
  TOP w0.305: PU23.2 29.84,70.53 R1009.1
N19149619: length 2.4
  TOP w0.305: PU23.4 28.84,69.97 28.5,70.31 R1013.1
  TOP w0.508: R1012.1 R1013.1
N19149820: length 3.2
  TOP w0.305: PU23.9 29.84,65.65 30.19,66.01 C8568.1
N19149890: length 39.8
  TOP w0.305: v2(30.35,63.63) 30.35,64.74 PU23.10
  TOP w0.762: R1011.1 7.25,54.55 D807.C v2(8.89,50.55)
  L3 w0.762: v2(30.35,63.63) 30.35,54.86 25.27,49.78 9.65,49.78 v2(8.89,50.55)
N19151513: length 4.1
  TOP w0.127: R176.2 CE25.1 81.47,14.68 Q4.B 81.48,13.19 R988.2
N19151587: length 20.6
  TOP w0.127: D802.C 100.35,5.06 97.16,8.26 85.3,8.26 R804.1
N19151589: length 3.6
  TOP w0.127: Q4.C 80.79,11.35 R804.2 R988.1
N19164313: length 4.2
  TOP w0.305: U909.2 32.62,133.84 32.64,133.86 v1(32.64,133.94)
  BOTTOM w0.508: v1(32.64,133.94) R91.2 33.26,133.92 33.26,133.03 C255.1 33.98,133.02 D3.A
N19164743: length 6.4
  TOP w0.305: v2(38.42,128.78) 36.52,130.68 U909.8
  BOTTOM w0.305: v2(38.42,128.78) 39.9,128.78 R1017.2
N19164772: length 2.1
  TOP w0.305: Q804.3 44,129.67 v2(43.94,129.73) ; v2(45.34,129.73) 45.3,129.69 Q804.1 ; Q804.2 44.65,129.72 v2(44.64,129.73)
N19164778: length 5.4
  TOP w0.305: U909.9 37.17,130.91 39.37,128.71 R1018.2
N19164928: length 8.1
  TOP w0.305: U909.10 37.82,131.09 39.05,129.86 42.54,129.86 Q804.4
N19165359: length 2.3
  TOP w0.305: Q805.3 42.03,132.9 v2(41.97,132.84) ; Q805.1 42.08,134.2 v2(41.97,134.3) ; Q805.2 v2(41.97,133.55)
N19165393: length 3.6
  TOP w0.305: U909.14 40.42,132 40.72,131.7 42.42,131.7 42.72,132 Q805.4
N19165428: length 2.4
  TOP w0.305: v2(39.12,131.32) U909.12
  BOTTOM w0.305: v2(39.12,131.32) 39.25,131.44 R1021.2
N19165431: length 4.1
  TOP w0.305: R1022.2 42.12,131.06 40.45,131.06 39.77,131.74 U909.13
N19165523: length 0.9
  BOTTOM w0.305: F2.2 v2(47.31,133.99)
  vias: v2(46.61,134.68) v2(46.61,133.29) v2(46.67,133.99) v2(47.31,134.68) v2(47.31,133.29)
N19176803: length 3.9
  TOP w0.305: U909.16 39.77,139.4 39.99,139.62 42.26,139.62 R1024.1
N19176821: length 3.1
  TOP w0.305: U909.15 40.42,137.19 v2(40.45,137.16)
  BOTTOM w0.305: v2(40.45,137.16) 40.21,137.4 R1023.1
N19177080: length 2.3
  TOP w0.305: v2(41.97,137.99) 42.08,137.88 Q806.1 ; Q806.3 42.03,136.58 v2(41.97,136.53) ; Q806.2 42.03,137.23 v2(41.97,137.29)
N19177140: length 0.9
  BOTTOM w0.305: F3.1 47.43,137.54 v2(47.37,137.48)
  vias: v2(46.67,138.3) v2(46.67,137.48) v2(46.67,136.78) v2(47.37,138.3) v2(47.37,136.78)
N19177464: length 5.5
  TOP w0.305: Q806.4 40.09,135.93 39.12,136.91 39.12,138.37 U909.17
N19177597: length 2.3
  TOP w0.305: v2(35.88,140.08) 35.76,140.2 Q807.3 ; Q807.2 v2(35.11,140.08) ; Q807.1 34.46,140.19 v2(34.35,140.08)
N19177683: length 2.3
  TOP w0.305: v2(38.04,139.7) 37.82,139.48 U909.19
  BOTTOM w0.305: R1027.1 v2(38.04,139.7)
N19177705: length 2.5
  TOP w0.305: U909.20 37.17,139.74 R1028.1
N19177745: length 2.5
  TOP w0.305: U909.21 36.52,140.72 Q807.4
N19198143: length 5.4
  TOP w0.508: v2(31.05,129.54) C847.1 31.61,128.76 31.99,129.14 R498.1
  BOTTOM w0.508: v2(31.05,129.54) v2(27.75,129.54)
N19198218: length 6.5
  TOP w0.508: R497.1 43.16,123.33 v2(43.18,123.32)
  BOTTOM w0.508: v2(43.18,123.32) v2(43.18,117.67)
N19198257: length 1.6
  TOP w0.508: PU30.2 C852.1
N19198264: length 1.8
  TOP w0.508: PU30.3 34.8,127.72 R501.1
N19198416: length 4.3
  TOP w0.508: C847.2 31.18,127.78 R498.2 R502.1 PU30.4
N19201900: length 1.7
  TOP w0.508: R1012.2 27.64,73.16 D815.C
N19202261: length 12.9
  TOP w1.016: v2(34.54,107.44) 35.1,106.89 C8571.1 R1033.1 35.1,104.19 34.67,103.76 Q808.C
  BOTTOM w1.016: v2(34.54,107.44) 34.67,107.44 34.89,107.67 C8578.1 R1046.1 v2(41.47,107.67) v2(42.8,107.67)
N19202480: length 1.5
  TOP w1.016: C8580.2 R1032.1
N19203123: length 9.1
  TOP w1.016: D817.C 31.81,106.63 33.4,105.03 R1033.2 33.36,104.65 33.36,101.55 Q808.B
N19203481: length 12.3
  BOTTOM w1.016: C8578.2 R1046.2 37.91,104.43 R1038.2 37.96,104.38 R1047.1 38.99,101.71 38.99,97.85 D818.REF
N19203514: length 2.2
  TOP w1.016: Q808.E 35.62,99.28 R1048.2
N19203544: length 4.3
  TOP w0.508: U39.1 35.43,94.04 35.47,94.08
  TOP w1.016: R1048.1 35.47,97.47 R1049.1 35.47,94.08
N19203613: length 12.1
  TOP w0.508: U39.2 34.16,93.85 33.88,94.14
  TOP w1.016: 33.88,94.14 R1049.2 33.88,96.68 v2(33.4,97.16)
  BOTTOM w1.016: C8582.1 32.51,103.01 32.51,98.04 v2(33.4,97.16) 34,96.55 D818.C
N19203897: length 3.8
  BOTTOM w1.016: R1038.1 36.31,104.44 C8582.2
N19489360: length 6.5
  TOP w0.091: U1.AE1 110.46,54.45 111.47,54.45 114.24,57.21 114.24,58.31 C86.2
N19489361: length 7.8
  TOP w0.091: C87.2 114.58,58.34 114.58,57.07 111.61,54.1 110.04,54.1 U1.AE2
N19489794: length 11.8
  TOP w0.091: R615.2 116.33,58.31 116.33,55.53 114.41,53.61 113.43,53.61 112.8,52.99 111.03,52.99 110.74,52.7 110.3,52.7 110.11,52.9 109.92,52.9 109.58,52.55 U1.Y3
N19489796: length 11.4
  TOP w0.091: U1.AA2 110.01,52.49 110.14,52.36 110.89,52.36 111.17,52.64 112.95,52.64 113.57,53.26 114.55,53.26 116.68,55.39 116.68,58.34 R616.2
N19489842: length 14
  TOP w0.091: U1.V3 109.58,51.69 109.89,52.01 110.11,52.01 110.3,51.82 111.25,51.82 111.41,51.97 113.59,51.97 114.09,52.48 115.03,52.48 118.31,55.76 118.31,58.3 C89.2
N19489844: length 13.6
  TOP w0.091: C93.2 118.66,58.35 118.66,55.61 115.18,52.13 114.24,52.13 113.73,51.63 111.55,51.63 111.4,51.47 110.14,51.47 110.01,51.6 U1.W2
N19492059: length 1.1
  TOP w0.508: 130.81,69.85 130.83,69.87 PR380.1
N19492096: length 14
  TOP w0.508: v2(134.68,72.58) PC382.1 PR351.1
  L3 w0.508: v2(133.35,60.77) 133.35,71.25 v2(134.68,72.58)
N19492104: length 2.1
  TOP w0.305: PC404.1 137.73,70.1 137.28,69.65 PU10.8
N19492532: length 3.9
  TOP w0.305: PU10.10 136.28,70.3 136.59,70.61 PR353.1
  TOP w0.508: PR353.1 PR351.2 PC382.2
N19492617: length 1.2
  TOP w0.508: PC383.2 140.57,69.28 PR355.2
N19494143: length 4.5
  TOP w0.254: PU14.6 140.24,39.18 140.37,39.05
  TOP w0.508: PR113.2 PR460.2 PC484.1 PR461.1 140.45,38.97 140.37,39.05
N19494174: length 18.6
  TOP w0.127: PC356.1 143.74,41.29
  TOP w0.508: v2(143.99,40.64) 143.99,41.04 143.74,41.29 PR339.1 ; PL180.2 132.74,38.16 132.23,38.67 v1(131.57,38.67)
  L3 w0.508: v1(131.57,38.67) 131.57,39.88 132.91,41.21 143.42,41.21 v2(143.99,40.64)
N19494227: length 2.8
  TOP w0.305: PC356.2 143.56,42.15 PR339.2
  TOP w0.508: PR339.2 PR337.1 PR344.2
N19494229: length 8.5
  TOP w0.508: PR460.1 142.85,37.24 v1(142.88,37.21)
  L3 w0.508: v1(142.88,37.21) 142.88,38.23 141.1,40.01 v2(137.07,40.01)
N19494349: length 1.1
  TOP w0.127: 139.44,38.65 139.47,38.68 PU14.5
  TOP w0.254: 139.44,38.65 139.63,38.46
  TOP w0.508: PR345.1 139.63,37.68 139.63,38.46
N19494355: length 1.2
  TOP w0.508: PR345.2 139.6,36.83 PC357.2
N19494368: length 2
  TOP w0.305: PR344.1 140.9,41.29 139.79,40.18 PU14.8
N19494464: length 1.7
  TOP w0.305: PC359.1 140.58,39.68 PU14.7
N19496414: length 1.2
  TOP w0.508: 37.91,72.45 37.83,72.53 PR615.1
N19496468: length 2.1
  TOP w0.305: PC682.1 37.59,79.44 38.05,78.98 PU40.8
N19496479: length 5.4
  TOP w0.305: PU40.11 37.67,77.48 37.34,77.15 37.34,75.96 PR607.1
  TOP w0.508: PR607.1 PC677.1 36.69,73.41 PR615.2
N19496629: length 4
  TOP w0.305: PU40.10 37.4,77.98 37.08,78.3 PR609.1
  TOP w0.508: PR608.2 PC683.2 PR609.1
N19496646: length 15.6
  TOP w0.508: v2(35.12,77.34) PC683.1 PR608.1
  L3 w0.508: v2(48.13,75.18) 37.27,75.18 v2(35.12,77.34)
N19496772: length 1.2
  TOP w0.508: PC691.2 38.42,82.25 PR613.2
N19531773: length 6.8
  TOP w0.127: R1040.1 29.53,156.54 29.53,156.23 C8595.1 29.53,155.56 29.53,155.27 R997.1 29.53,154.61 29.53,154.43 29.65,154.31 32,154.31 32.32,153.99 32.58,153.99 32.69,154.1 U27.11
N19531775: length 7.2
  TOP w0.127: U27.12 32.71,153.6 32.58,153.73 32.19,153.73 31.88,154.05 29.53,154.05 29.27,154.31 29.27,154.54 R996.1 29.21,155.27 29.21,155.56 C8596.1 29.21,156.23 29.21,156.54 R1039.1
N19531789: length 3.6
  TOP w0.254: U27.1 37.51,152.1 v2(37.66,151.96)
  BOTTOM w0.508: R999.2 R998.1 36.81,151.96 v2(37.66,151.96)
N19531805: length 3.1
  TOP w0.254: U27.14 32.39,152.6 32.07,152.27
  TOP w0.508: R991.2 32.07,152.27
N19532107: length 2.2
  TOP w0.254: U27.10 33.93,155.56 33.72,155.77
  TOP w0.508: 33.72,155.77 33.37,155.77 C8557.1
N19561994: length 7.5
  TOP w0.305: 62.61,78.23 62.48,78.36 57.34,78.36 56.82,77.84 PC364.1 56.94,77.22 PR340.1
N19562052: length 3
  TOP w0.305: PR347.2 PR338.1 PR340.2 56.09,77.1 PC364.2
N19562054: length 1.8
  TOP w0.305: PU15.2 58.74,72.14 v2(58.55,71.95)
  BOTTOM w0.508: PR463.1 58.48,72.01 v2(58.55,71.95)
N19562098: length 2.7
  TOP w0.305: PR464.1 PC366.1 57.93,72.47 58.24,72.78 PU15.1
N19562174: length 1.8
  TOP w0.305: PR346.1 60.33,75.63 59.74,75.04 PU15.5
N19562180: length 1.5
  TOP w0.508: PC365.2 61.85,75.36 PR346.2
N19562193: length 1.3
  TOP w0.305: PU15.8 56.95,74.42 PR347.1
N19562289: length 1.8
  TOP w0.305: PC369.1 58.67,76.03 58.67,74.99 58.74,74.93 PU15.7
N19563922: length 7.3
  TOP w0.305: PR341.1 68.37,77.35 PC378.1 68.19,78.16 68.45,78.42 73.79,78.42
N19563980: length 3
  TOP w0.305: PR349.2 PR342.1 PR341.2 67.52,77.22 67.7,77.41 PC378.2
N19563982: length 2.1
  TOP w0.305: v2(69.79,71.95) 69.98,72.14 PU16.2
  BOTTOM w0.508: PR466.1 v2(69.79,71.95)
N19564102: length 1.9
  TOP w0.305: PU16.5 70.98,75.47 PR348.1
N19564108: length 1.4
  TOP w0.508: PR348.2 72.9,75.74 PC384.2
N19564121: length 1.1
  TOP w0.305: PU16.8 68.44,74.55 PR349.1
N19564217: length 1.8
  TOP w0.305: PC389.1 69.79,76.03 69.79,75.12 69.98,74.93 PU16.7
N19565593: length 14.9
  TOP w0.254: PC397.1 97.23,87.23 PR343.1
  TOP w0.305: PC393.1 98.79,96.86 98.79,96.63 98.36,96.2 96.2,96.2 v1(96.01,96.01) ; PC397.1 96.25,87.23 v1(95.82,86.8)
  L3 w0.305: v1(96.01,96.01) 96.08,95.95 96.08,92.39 95.63,91.95 95.63,87 v1(95.82,86.8)
N19565653: length 20.8
  TOP w0.508: v2(95.31,92.96) 96.39,94.04 PR469.1 ; RP1129.2 101.76,82.08 101.15,81.46 v2(98.25,81.46)
  L3 w0.508: v2(95.31,92.96) 94.81,92.46 94.81,83.27 95.78,82.3 97.41,82.3 v2(98.25,81.46)
N19565684: length 3
  TOP w0.254: PC397.2 96.95,87.72 97.22,88 97.24,88 PR343.2
  TOP w0.508: PR354.1 97.04,89 ; 97.04,89 PR356.2 ; 97.04,89 97.04,88.28 PR343.2
N19565697: length 2.4
  TOP w0.254: PU17.1 101.09,90.5 100.3,89.71 PC399.1 PR470.1
N19565773: length 2.4
  TOP w0.254: 99.33,92.44 99.77,92 PU17.5
  TOP w0.508: PR350.1 99.11,92.66 99.33,92.44
N19565779: length 1.1
  TOP w0.508: PR350.2 100.02,94.03 100.04,94.04 101.03,94.04 PC398.2
N19565792: length 2.2
  TOP w0.254: PR356.1 98.56,89.86 99.2,90.5 PU17.8
N19565888: length 1.5
  TOP w0.254: PU17.7 98.41,91 PC400.1
N19599376: length 1.3
  TOP w0.762: C245.2 R251.1
N19599378: length 1.3
  TOP w0.762: C244.2 R252.1
N19599380: length 1.3
  TOP w0.762: C243.2 R253.1
N19599382: length 1.3
  TOP w0.762: C242.2 R261.1
N19599384: length 23.6
  TOP w0.762: v2(73.41,137.16) R252.2 ; R251.2 v2(70.1,137.16) 70.1,137.54 69.34,138.3 v2(66.55,138.3) ; R253.2 v2(77.72,137.16) ; R261.2 v2(81.53,137.16)
  BOTTOM w0.762: C237.1 66.04,138.81 v2(66.55,138.3) ; v2(81.53,137.16) v2(77.72,137.16) v2(73.41,137.16) v2(70.1,137.16)
N19664892: length 1.9
  TOP w0.127: SR65.1 105.33,79.38 U5.7
N19665679: length 17.5
  TOP w0.127: v1(137.52,91.29) 137.74,91.06 138.54,91.06 SR157.2 SC520.1 140.22,91.12 141.99,91.12 142.94,92.08 142.94,92.33
  BOTTOM w0.127: v1(137.52,91.29) 137.29,91.06 131.13,91.06 129.54,89.47 127.75,89.47 SR158.2
N19665693: length 17.2
  TOP w0.127: J1.3 141.99,90.74 140.16,90.74 SC521.1 SR153.2 138.61,90.81 137.67,90.81 v1(137.49,90.63)
  BOTTOM w0.127: SR159.2 127.62,89.15 129.67,89.15 131.32,90.81 137.31,90.81 v1(137.49,90.63)
N19837833: length 1.3
  TOP w0.762: C251.2 R246.1
N19837837: length 1.3
  TOP w0.762: C252.2 R244.1
N19837859: length 1.3
  TOP w0.762: C253.2 R245.1
N19837869: length 1.3
  TOP w0.762: C250.2 R241.1
N19837873: length 31.8
  TOP w0.762: v2(103.89,137.92) R245.2 ; R246.2 v2(109.86,137.92) ; R241.2 v2(113.41,137.92) ; R244.2 v2(94.61,137.92)
  BOTTOM w0.762: v2(94.61,137.92) v2(103.89,137.92) v2(109.86,137.92) v2(113.41,137.92) 118.11,137.92 119.76,139.57 C288.1
N19838616: length 1.3
  TOP w0.762: C258.2 R248.1
N19838620: length 1.3
  TOP w0.762: C257.2 R247.1
N19838624: length 1.3
  TOP w0.762: C256.2 R250.1
N19838628: length 1.3
  TOP w0.762: C254.2 R249.1
N19838632: length 25.2
  TOP w0.762: R248.2 v2(90.55,137.29) ; v2(106.81,136.78) R247.2 ; R249.2 v2(100.33,136.78) ; R250.2 v2(97.66,136.78)
  BOTTOM w0.762: 90.58,137.29 90.58,137.95 92.84,140.21 C294.1 ; 90.58,137.29 v2(90.55,137.29) ; 90.58,137.29 93.47,137.29 93.98,136.78 v2(97.66,136.78) v2(100.33,136.78) v2(106.81,136.78)
N19974700: length 2.5
  TOP w0.127: TP3.1 70.74,98.17 71.82,97.09 E1U1.23
N20037364: length 2.4
  TOP w0.127: U27.8 34.92,155.32 34.8,155.45 34.8,156.92 R357.1
N20037385: length 2.4
  TOP w0.127: U27.9 34.42,155.33 34.54,155.45 34.54,156.99 R358.1
N20084108: length 1.9
  BOTTOM w0.127: SR62.2 SR609.1 TP17.1
N20170813: length 26.8
  TOP w0.305: v2(27.91,63.55) C29.1 28.84,63.56 PU23.7
  TOP w0.762: R1045.1 v2(13.59,52.2)
  L3 w0.762: v2(27.91,63.55) 27.91,55.6 24.51,52.2 v2(13.59,52.2)
N20751065: length 3.9
  TOP w0.127: R1001.2 44.02,13.26 Q3.B 44,14.62 CE23.1 R179.1
N20751067: length 3.6
  TOP w0.127: R1001.1 R802.2 43.33,11.41 Q3.C
N20751191: length 18.3
  TOP w0.127: R802.1 45.53,9.72 46.74,8.51 57.53,8.51 60.35,5.69 D806.C
N20751626: length 4.1
  TOP w0.127: R180.2 CE33.1 60.77,14.62 Q8.B 60.78,13.19 R1003.2
N20751628: length 4.1
  TOP w0.127: R1002.2 55.57,13.19 Q7.B 55.56,14.62 CE31.1 R189.1
N20751630: length 3.6
  TOP w0.127: R1002.1 R806.2 54.88,11.35 Q7.C
N20751632: length 3.6
  TOP w0.127: R1003.1 R807.2 60.09,11.35 Q8.C
N20751867: length 16.3
  TOP w0.127: D822.C 70.35,5.85 68.58,7.62 61.09,7.62 58.21,10.49 R806.1
N20751906: length 14.9
  TOP w0.127: R807.1 63.96,8.89 68.58,8.89 71.75,5.71 71.75,3.81 71.24,3.3 D823.C
N20752359: length 4
  TOP w0.127: R1005.2 71.32,13.26 Q10.B 71.31,14.68 CE37.1 R195.2
N20752361: length 4.1
  TOP w0.127: R1004.2 66.11,13.19 Q9.B 66.1,14.56 CE35.1 R196.1
N20752363: length 3.6
  TOP w0.127: Q9.C 65.42,11.35 R808.2 R1004.1
N20752365: length 3.6
  TOP w0.127: Q10.C 70.63,11.41 R811.2 R1005.1
N20752600: length 15.9
  TOP w0.127: D824.C 80.35,6.01 78.74,7.62 71.12,7.62 68.25,10.49 R808.1
N20752639: length 14
  TOP w0.127: D825.C 80.77,3.3 81.41,3.94 81.41,6.22 78.74,8.89 74.5,8.89 R811.1
N20820874: length 1.4
  TOP w0.254: R985.1 34.97,150.16 35.43,150.61 U27.19
N20820880: length 1.2
  TOP w0.254: U27.20 35.92,149.95 R995.1
N20912001: length 3.4
  BOTTOM w0.127: SR89.2 122.87,82.41 122.87,82.93 121.45,84.36 U66.112
N20912029: length 4.1
  BOTTOM w0.102: U66.113 121.2,84.23 121.28,84.14
  BOTTOM w0.127: 121.28,84.14 122.56,82.86 122.56,82.35 SR91.2
N20914921: length 3.8
  BOTTOM w0.102: 120.7,84.18 U66.115
  BOTTOM w0.127: SR93.2 121.09,82.41 121.09,82.8 120.65,83.25 120.65,84.14 120.7,84.18
N20914922: length 3
  BOTTOM w0.127: U66.116 120.4,84.71 120.4,83.12 120.84,82.68 120.84,82.41 SR94.2
N24238736: length 6.1
  TOP w0.127: E1R12.1 84.27,95.24 80.63,95.24 80.48,95.09 E1U1.58
N24238738: length 5.8
  TOP w0.127: E1U1.59 84.45,95.49 85.12,94.82 E1R13.1
N24238740: length 1.5
  TOP w0.127: E1U1.54 81.19,93.49 E1R14.2
N24238742: length 1.6
  TOP w0.127: E1U1.27 v1(73.11,95.49)
  BOTTOM w0.102: v1(73.11,95.49) 72.92,95.31 E1R15.2
N24239054: length 4.4
  TOP w0.127: E1U1.21 71.91,97.89 71.12,98.68 71.12,100.41 70.56,100.97 TP2.1
N26017682: length 9.3
  BOTTOM w0.089: 117.05,84.21 117.2,84.36 U66.129
  BOTTOM w0.127: SR610.2 113.79,77.8 115.91,79.92 115.91,83.07 117.05,84.21
N26017689: length 8.3
  BOTTOM w0.089: U66.128 117.45,84.24 117.24,84.03
  BOTTOM w0.127: SR609.2 114.74,78.3 116.16,79.71 116.16,82.95 117.24,84.03
N26017934: length 1
  BOTTOM w0.127: SR610.1 TP18.1
N26023442: length 1
  BOTTOM w0.127: SR136.1 TP20.1
N26023467: length 1
  BOTTOM w0.127: SR138.1 TP19.1
N1912991617: length 3.7
  TOP w0.102: U1.AE28 99.12,54.32 98.7,54.73 98.3,54.73 97.51,55.52 97.51,56.87 TP8.1
N1912991621: length 3.8
  TOP w0.102: U1.AF21 102.31,54.88 102.31,55.31 102.41,55.41 102.41,55.83 101.98,56.26 100.52,56.26 TP7.1
N1912991629: length 4.6
  TOP w0.102: TP6.1 110.68,57.28 109.86,57.28 108.89,56.31 108.89,55.4 108.24,54.75 U1.AF6

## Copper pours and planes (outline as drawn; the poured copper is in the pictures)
AVDDH_PHY0 on BOTTOM (solid shape): 80.49,101.45 80.49,100.94 80.44,100.89 79.78,100.89 79.68,100.79 79.68,100.41 79.58,100.31 79.22,100.31 79.1,100.44 79.1,100.77 78.97,100.89 77.32,100.89 77.24,100.82 77.24,100.46 77.11,100.34 76.78,100.34 76.66,100.46 76.66,100.74 76.5,100.89 74.68,100.89 74.57,100.79 74.57,100.49 74.45,100.36 74.17,100.36 74.09,100.44 74.09,101.27 74.32,101.5 80.44,101.5
AVDDH_PLL0 on BOTTOM (solid shape): 81.38,100.06 81.38,99.57 81.36,99.55 80.62,99.55 80.52,99.45 80.52,98.28 79.48,97.24 79.25,97.24 79.1,97.39 79.1,97.59 79.96,98.46 79.96,100.06 80.01,100.11 81.33,100.11
AVDDL_PHY0 on BOTTOM (solid shape): 73.96,100.84 73.96,99.83 74.07,99.73 78.77,99.73 78.82,99.67 78.82,98.94 78.77,98.89 73.61,98.89 73.36,99.14 73.36,100.85 73.43,100.92 73.89,100.92
AVDDL_PLL0 on BOTTOM (solid shape): 85.6,97.82 85.6,96.93 85.57,96.91 83.9,96.91 83.54,97.26 81.61,97.26 81.05,96.7 80.82,96.7 80.64,96.88 80.64,97.06 81.51,97.92 85.5,97.92
GND on TOP (solid shape): 66.62,96.98 65.82,96.98 65.82,100.41 66.62,100.41
